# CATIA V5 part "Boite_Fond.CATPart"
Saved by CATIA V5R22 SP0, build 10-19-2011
Part number: Boite_Fond
Bounding box of the stored display mesh (mm): x -88 to 88, y -59.5 to 59.5, z 0 to 5
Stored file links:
  D:\CAO_PER_MODIF_2025\CAO_PER_pick&place_2024P\Sous_Ensemble_Boite\Boite\Boite_Fond.CATPart
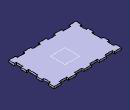
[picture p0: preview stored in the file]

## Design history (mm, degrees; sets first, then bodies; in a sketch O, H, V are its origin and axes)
Body1 (main body)
  Sketch1 on xy-plane, origin (0, 0, 0), H (1, 0, 0), V (0, 1, 0)
    line L1 (-88, 59.5) -> (88, 59.5)
    line L2 (88, 59.5) -> (88, -59.5)
    line L3 (88, -59.5) -> (-88, -59.5)
    line L4 (-88, -59.5) -> (-88, 59.5)
    length L1 = 176
    length L2 = 119
    horizontal: L1 H, L3 H
    vertical: L2 V, L4 V
    symmetry: L4 L2 V, L3 L1 H
  Pad1: profile Sketch1, direction (0, 0, 1), length 5
  Sketch2 on end face of Pad1, origin (0, 0, 5), H (1, 0, 0), V (0, 1, 0)
    point P1 (-70, 59.5)
    line L1 (-70, 59.5) -> (-50, 59.5)
    line L2 (-50, 59.5) -> (-50, 54.5)
    line L3 (-50, 54.5) -> (-70, 54.5)
    line L4 (-70, 54.5) -> (-70, 59.5)
    point P2 (-50, 59.5)
    point P3 (-50, 54.5)
    point P4 (-70, 54.5)
    reference projected line E1 (-88, 67) -> (-88, -67) from edge [face of Pad1 from Sketch1.L4 | end face of Pad1]
    reference projected line E2 (98, 59.5) -> (-98, 59.5) from edge [face of Pad1 from Sketch1.L1 | end face of Pad1]
    point P5 (-70, -59.5)
    point P6 (-50, -59.5)
    point P7 (-50, -54.5)
    point P8 (-70, -54.5)
    line L5 (-70, -59.5) -> (-50, -59.5)
    line L6 (-50, -59.5) -> (-50, -54.5)
    line L7 (-50, -54.5) -> (-70, -54.5)
    line L8 (-70, -54.5) -> (-70, -59.5)
    distance E1 L4 = 18
    length L1 = 20
    length L2 = 5
    horizontal: L1 H, L3 H
    vertical: L2 V, L4 V
    coincidence: E2 L1
    symmetry: P1 P5 H, P2 P6 H, P3 P7 H, P4 P8 H, L1 L5 H, L2 L6 H, L3 L7 H, L4 L8 H
  Pocket1: profile Sketch2, direction (0, 0, -1), through (limit type 6)
  RectPattern1: of Pocket1, direction 1 instances 4, spacing 40, along edge [face of Pad1 from Sketch1.L1 | end face of Pad1] reversed
  Sketch3 on end face of Pad1, origin (0, 0, 5), H (1, 0, 0), V (0, 1, 0)
    point P1 (-88, 44.5)
    line L1 (-88, 44.5) -> (-83, 44.5)
    line L2 (-83, 44.5) -> (-83, 27.5)
    line L3 (-83, 27.5) -> (-88, 27.5)
    line L4 (-88, 27.5) -> (-88, 44.5)
    point P2 (-83, 44.5)
    point P3 (-83, 27.5)
    point P4 (-88, 27.5)
    reference projected line E1 (-88, 67) -> (-88, -67) from edge [face of Pad1 from Sketch1.L4 | end face of Pad1]
    reference projected line E2 (98, 59.5) -> (-98, 59.5) from edge [face of Pad1 from Sketch1.L1 | end face of Pad1]
    point P5 (88, 44.5)
    point P6 (83, 44.5)
    point P7 (83, 27.5)
    point P8 (88, 27.5)
    line L5 (88, 44.5) -> (83, 44.5)
    line L6 (83, 44.5) -> (83, 27.5)
    line L7 (83, 27.5) -> (88, 27.5)
    line L8 (88, 27.5) -> (88, 44.5)
    distance L1 E2 = 15
    length L4 = 17
    length L1 = 5
    horizontal: L1 H, L3 H
    vertical: L2 V, L4 V
    coincidence: L4 E1
    symmetry: P1 P5 V, P2 P6 V, P3 P7 V, P4 P8 V, L1 L5 V, L2 L6 V, L3 L7 V, L4 L8 V
  Pocket2: profile Sketch3, direction (0, 0, -1), through (limit type 6)
  Mirror1: of Pocket2, about zx-plane
  Sketch4 on end face of Pad1, origin (0, 0, 5), H (1, 0, 0), V (0, 1, 0)
    line L1 (-88, 12.5) -> (-83, 12.5)
    line L2 (-83, 12.5) -> (-83, -12.5)
    line L3 (-83, -12.5) -> (-88, -12.5)
    line L4 (-88, -12.5) -> (-88, 12.5)
    point P5 (88, 12.5)
    line L5 (88, 12.5) -> (83, 12.5)
    line L6 (83, 12.5) -> (83, -12.5)
    line L7 (83, -12.5) -> (88, -12.5)
    line L8 (88, -12.5) -> (88, 12.5)
    point P7 (83, -12.5)
    reference projected line E1 (-88, 59.5) -> (-88, -59.5) from edge [face of Pad1 from Sketch1.L4 | end face of Pad1]
    reference projected line E2 (83, 44.5) -> (83, 27.5) from edge [end face of Pad1 | face of Pocket2 from Sketch3.L6]
    distance L5 L7 = 25
    horizontal: L1 H, L3 H, L5 H, L7 H
    vertical: L2 V, L4 V, L6 V, L8 V
    coincidence: P5 L1, P7 L3, L4 E1, L6 E2
    symmetry: L5 L7 H, L1 L3 H, L6 L2 V, L4 L8 V
  Pocket3: profile Sketch4, direction (0, 0, -1), through (limit type 6)
  Plane1: type Offset, RefPlane start face of Pad1, Offset 0, reversed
